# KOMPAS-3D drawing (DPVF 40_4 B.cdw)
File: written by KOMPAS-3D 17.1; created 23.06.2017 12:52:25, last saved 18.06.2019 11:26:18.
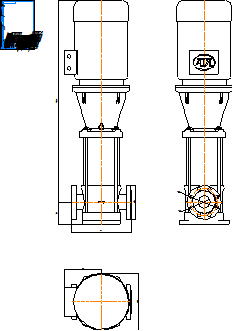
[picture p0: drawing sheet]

Sheet 1: A4, portrait

Title block, sheet 1: name: DPVF 40_4 B; material: Внимание! Данный продукт является объектом авторского права ООО «Торговый Дом АДЛ». / Запрещается изменение, копирование, распространение / (в том числе путем копирования на другие сайты и ресурсы в Интернете) / или любое иное использование информации и объектов без предварительного / согласия правообладателя (ООО «Торговый Дом АДЛ»).; scale: 1:1; sheets: 1; organisation: ООО "Торговый дом АДЛ"; sheet format: A4; stored path: C:\Клочков АВ\Насосы\DP PAMS\DPVF 40\Компас 2d\DPVF 40_4 B.cdw

Views: Спереди 1
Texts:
  Клочков АВ
  ООО АДЛ ГРУПП
Dimensions and other numbers on the sheet: 365; 223; 350; 209,6; 1234,5; 140; 168,1; 76,2; 1:1; 1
